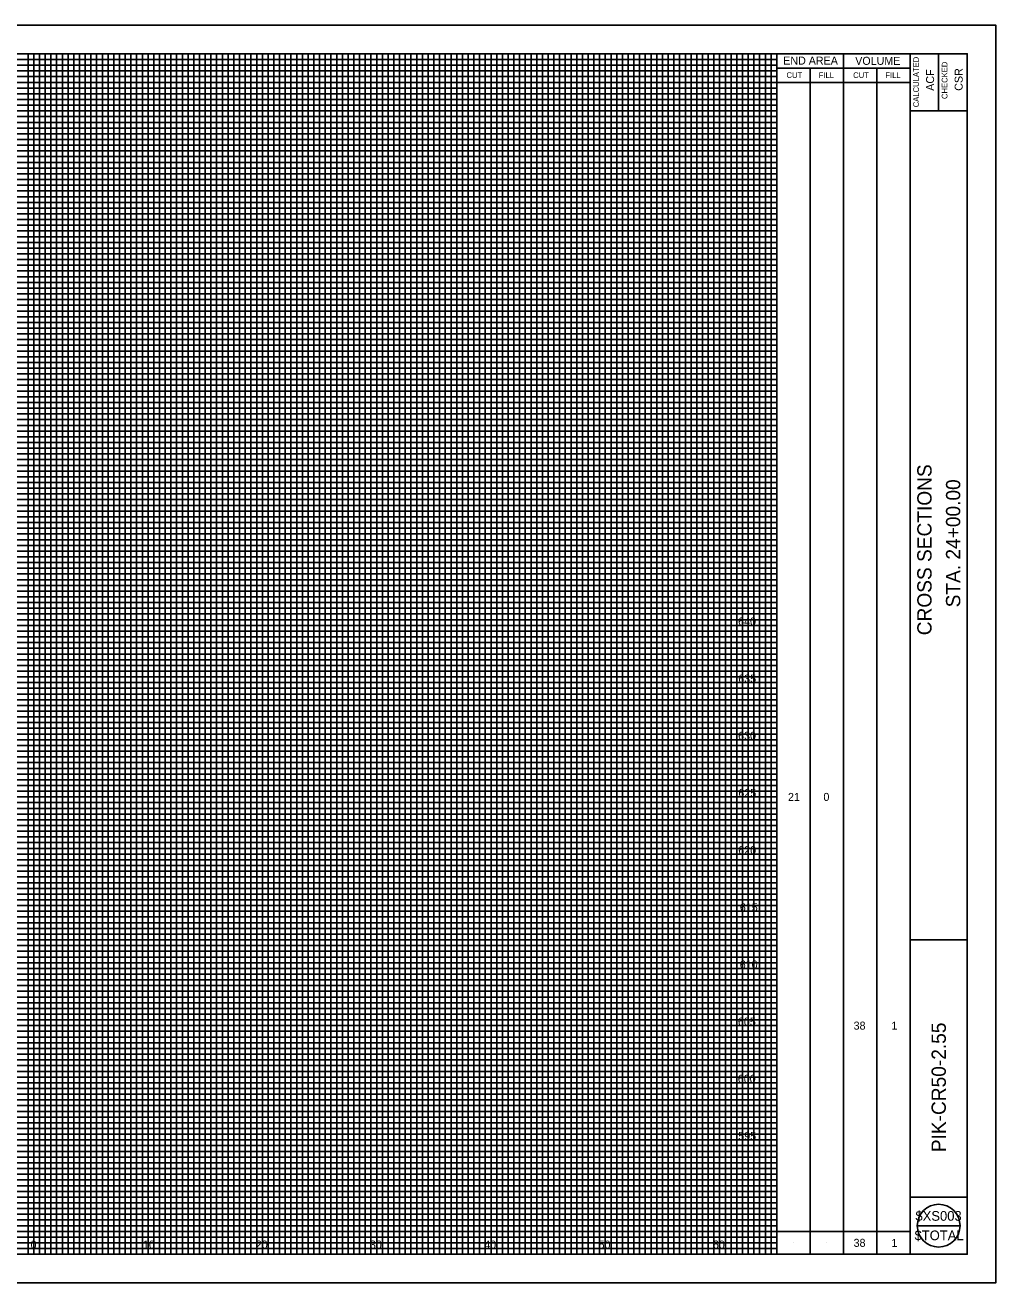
# Model space of a CAD drawing. Extents: x 1858928 to 1859278, y 421672 to 422012.
# Drawn here: x 1859012.6 to 1859097.5, y 421901.6 to 422011.6 of the extents above; entities that cross this region are included whole.
import ezdxf

# ---------------------------------------------------------------- set-up
doc = ezdxf.new("R2010")
doc.units = 0
for name, color, linetype in [('SH_Border', 7, 'Continuous'), ('SH_Cut_Line', 7, 'Continuous'), ('SH_Data', 7, 'Continuous'), ('SH_Major_Grid_Line', 7, 'Continuous'), ('SH_Minor_Grid_Line', 7, 'Continuous'), ('SH_Text', 7, 'Continuous')]:
    doc.layers.add(name, color=color, linetype=linetype)

msp = doc.modelspace()

# ---------------------------------------------------------------- linework, layer by layer
at = {"layer": 'SH_Border'}
for p, q in [((1859090.03, 421904.11), (1859090.03, 422009.11)), ((1859092.53, 422009.11), (1859092.53, 422004.11)), ((1859090.03, 422004.11), (1859095.03, 422004.11)), ((1859090.03, 421931.61), (1859095.03, 421931.61)), ((1859090.03, 421909.11), (1859095.03, 421909.11))]:
    msp.add_line(p, q, dxfattribs=at)
msp.add_lwpolyline([(1858937.53, 422009.11), (1859095.03, 422009.11), (1859095.03, 421904.11), (1858937.53, 421904.11)], close=True, dxfattribs=at)
at = {"layer": 'SH_Cut_Line'}
msp.add_lwpolyline([(1858927.53, 421901.61), (1859097.53, 421901.61), (1859097.53, 422011.61), (1858927.53, 422011.61)], close=True, dxfattribs=at)
at = {"layer": 'SH_Data'}
for p, q in [((1859078.37, 421904.11), (1859078.37, 422009.11)), ((1859084.2, 421904.11), (1859084.2, 422009.11)), ((1859078.37, 422007.86), (1859090.03, 422007.86)), ((1859081.28, 421904.11), (1859081.28, 422007.86)), ((1859087.12, 421904.11), (1859087.12, 422007.86)), ((1859078.37, 422006.61), (1859090.03, 422006.61)), ((1859078.37, 421906.11), (1859090.03, 421906.11)), ((1859090.66, 421906.61), (1859094.41, 421906.61)), ((1859079.83, 421905.11), (1859079.83, 421905.11)), ((1859082.74, 421905.11), (1859082.74, 421905.11)), ((1859085.66, 421905.11), (1859085.66, 421905.11)), ((1859088.58, 421905.11), (1859088.58, 421905.11))]:
    msp.add_line(p, q, dxfattribs=at)
msp.add_circle((1859092.53, 421906.61), 1.87, dxfattribs=at)
at = {"layer": 'SH_Major_Grid_Line'}
for p, q in [((1859013.37, 421904.11), (1859013.37, 422009.11)), ((1859018.37, 421904.11), (1859018.37, 422009.11)), ((1859023.37, 421904.11), (1859023.37, 422009.11)), ((1859028.37, 421904.11), (1859028.37, 422009.11)), ((1859033.37, 421904.11), (1859033.37, 422009.11)), ((1859038.37, 421904.11), (1859038.37, 422009.11)), ((1859043.37, 421904.11), (1859043.37, 422009.11)), ((1859048.37, 421904.11), (1859048.37, 422009.11)), ((1859053.37, 421904.11), (1859053.37, 422009.11)), ((1859058.37, 421904.11), (1859058.37, 422009.11)), ((1859063.37, 421904.11), (1859063.37, 422009.11)), ((1859068.37, 421904.11), (1859068.37, 422009.11)), ((1859073.37, 421904.11), (1859073.37, 422009.11)), ((1858943.37, 422004.11), (1859078.37, 422004.11)), ((1858943.37, 421999.11), (1859078.37, 421999.11)), ((1858943.37, 421994.11), (1859078.37, 421994.11)), ((1858943.37, 421989.11), (1859078.37, 421989.11)), ((1858943.37, 421984.11), (1859078.37, 421984.11)), ((1858943.37, 421979.11), (1859078.37, 421979.11)), ((1858943.37, 421974.11), (1859078.37, 421974.11)), ((1858943.37, 421969.11), (1859078.37, 421969.11)), ((1858943.37, 421964.11), (1859078.37, 421964.11)), ((1858943.37, 421959.11), (1859078.37, 421959.11)), ((1858943.37, 421954.11), (1859078.37, 421954.11)), ((1858943.37, 421949.11), (1859078.37, 421949.11)), ((1858943.37, 421944.11), (1859078.37, 421944.11)), ((1858943.37, 421939.11), (1859078.37, 421939.11)), ((1858943.37, 421934.11), (1859078.37, 421934.11)), ((1858943.37, 421929.11), (1859078.37, 421929.11)), ((1858943.37, 421924.11), (1859078.37, 421924.11)), ((1858943.37, 421919.11), (1859078.37, 421919.11)), ((1858943.37, 421914.11), (1859078.37, 421914.11)), ((1858943.37, 421909.11), (1859078.37, 421909.11))]:
    msp.add_line(p, q, dxfattribs=at)
at = {"layer": 'SH_Minor_Grid_Line'}
for p, q in [((1858943.37, 422008.61), (1859078.37, 422008.61)), ((1859012.87, 421904.11), (1859012.87, 422009.11)), ((1859013.87, 421904.11), (1859013.87, 422009.11)), ((1859014.37, 421904.11), (1859014.37, 422009.11)), ((1859014.87, 421904.11), (1859014.87, 422009.11)), ((1859015.37, 421904.11), (1859015.37, 422009.11)), ((1859015.87, 421904.11), (1859015.87, 422009.11)), ((1859016.37, 421904.11), (1859016.37, 422009.11)), ((1859016.87, 421904.11), (1859016.87, 422009.11)), ((1859017.37, 421904.11), (1859017.37, 422009.11)), ((1859017.87, 421904.11), (1859017.87, 422009.11)), ((1859018.87, 421904.11), (1859018.87, 422009.11)), ((1859019.37, 421904.11), (1859019.37, 422009.11)), ((1859019.87, 421904.11), (1859019.87, 422009.11)), ((1859020.37, 421904.11), (1859020.37, 422009.11)), ((1859020.87, 421904.11), (1859020.87, 422009.11)), ((1859021.37, 421904.11), (1859021.37, 422009.11)), ((1859021.87, 421904.11), (1859021.87, 422009.11)), ((1859022.37, 421904.11), (1859022.37, 422009.11)), ((1859022.87, 421904.11), (1859022.87, 422009.11)), ((1859023.87, 421904.11), (1859023.87, 422009.11)), ((1859024.37, 421904.11), (1859024.37, 422009.11)), ((1859024.87, 421904.11), (1859024.87, 422009.11)), ((1859025.37, 421904.11), (1859025.37, 422009.11)), ((1859025.87, 421904.11), (1859025.87, 422009.11)), ((1859026.37, 421904.11), (1859026.37, 422009.11)), ((1859026.87, 421904.11), (1859026.87, 422009.11)), ((1859027.37, 421904.11), (1859027.37, 422009.11)), ((1859027.87, 421904.11), (1859027.87, 422009.11)), ((1859028.87, 421904.11), (1859028.87, 422009.11)), ((1859029.37, 421904.11), (1859029.37, 422009.11)), ((1859029.87, 421904.11), (1859029.87, 422009.11)), ((1859030.37, 421904.11), (1859030.37, 422009.11)), ((1859030.87, 421904.11), (1859030.87, 422009.11)), ((1859031.37, 421904.11), (1859031.37, 422009.11)), ((1859031.87, 421904.11), (1859031.87, 422009.11)), ((1859032.37, 421904.11), (1859032.37, 422009.11)), ((1859032.87, 421904.11), (1859032.87, 422009.11)), ((1859033.87, 421904.11), (1859033.87, 422009.11)), ((1859034.37, 421904.11), (1859034.37, 422009.11)), ((1859034.87, 421904.11), (1859034.87, 422009.11)), ((1859035.37, 421904.11), (1859035.37, 422009.11)), ((1859035.87, 421904.11), (1859035.87, 422009.11)), ((1859036.37, 421904.11), (1859036.37, 422009.11)), ((1859036.87, 421904.11), (1859036.87, 422009.11)), ((1859037.37, 421904.11), (1859037.37, 422009.11)), ((1859037.87, 421904.11), (1859037.87, 422009.11)), ((1859038.87, 421904.11), (1859038.87, 422009.11)), ((1859039.37, 421904.11), (1859039.37, 422009.11)), ((1859039.87, 421904.11), (1859039.87, 422009.11)), ((1859040.37, 421904.11), (1859040.37, 422009.11)), ((1859040.87, 421904.11), (1859040.87, 422009.11)), ((1859041.37, 421904.11), (1859041.37, 422009.11)), ((1859041.87, 421904.11), (1859041.87, 422009.11)), ((1859042.37, 421904.11), (1859042.37, 422009.11)), ((1859042.87, 421904.11), (1859042.87, 422009.11)), ((1859043.87, 421904.11), (1859043.87, 422009.11)), ((1859044.37, 421904.11), (1859044.37, 422009.11)), ((1859044.87, 421904.11), (1859044.87, 422009.11)), ((1859045.37, 421904.11), (1859045.37, 422009.11)), ((1859045.87, 421904.11), (1859045.87, 422009.11)), ((1859046.37, 421904.11), (1859046.37, 422009.11)), ((1859046.87, 421904.11), (1859046.87, 422009.11)), ((1859047.37, 421904.11), (1859047.37, 422009.11)), ((1859047.87, 421904.11), (1859047.87, 422009.11)), ((1859048.87, 421904.11), (1859048.87, 422009.11)), ((1859049.37, 421904.11), (1859049.37, 422009.11)), ((1859049.87, 421904.11), (1859049.87, 422009.11)), ((1859050.37, 421904.11), (1859050.37, 422009.11)), ((1859050.87, 421904.11), (1859050.87, 422009.11)), ((1859051.37, 421904.11), (1859051.37, 422009.11)), ((1859051.87, 421904.11), (1859051.87, 422009.11)), ((1859052.37, 421904.11), (1859052.37, 422009.11)), ((1859052.87, 421904.11), (1859052.87, 422009.11)), ((1859053.87, 421904.11), (1859053.87, 422009.11)), ((1859054.37, 421904.11), (1859054.37, 422009.11)), ((1859054.87, 421904.11), (1859054.87, 422009.11)), ((1859055.37, 421904.11), (1859055.37, 422009.11)), ((1859055.87, 421904.11), (1859055.87, 422009.11)), ((1859056.37, 421904.11), (1859056.37, 422009.11)), ((1859056.87, 421904.11), (1859056.87, 422009.11)), ((1859057.37, 421904.11), (1859057.37, 422009.11)), ((1859057.87, 421904.11), (1859057.87, 422009.11)), ((1859058.87, 421904.11), (1859058.87, 422009.11)), ((1859059.37, 421904.11), (1859059.37, 422009.11)), ((1859059.87, 421904.11), (1859059.87, 422009.11)), ((1859060.37, 421904.11), (1859060.37, 422009.11)), ((1859060.87, 421904.11), (1859060.87, 422009.11)), ((1859061.37, 421904.11), (1859061.37, 422009.11)), ((1859061.87, 421904.11), (1859061.87, 422009.11)), ((1859062.37, 421904.11), (1859062.37, 422009.11)), ((1859062.87, 421904.11), (1859062.87, 422009.11)), ((1859063.87, 421904.11), (1859063.87, 422009.11)), ((1859064.37, 421904.11), (1859064.37, 422009.11)), ((1859064.87, 421904.11), (1859064.87, 422009.11)), ((1859065.37, 421904.11), (1859065.37, 422009.11)), ((1859065.87, 421904.11), (1859065.87, 422009.11)), ((1859066.37, 421904.11), (1859066.37, 422009.11)), ((1859066.87, 421904.11), (1859066.87, 422009.11)), ((1859067.37, 421904.11), (1859067.37, 422009.11)), ((1859067.87, 421904.11), (1859067.87, 422009.11)), ((1859068.87, 421904.11), (1859068.87, 422009.11)), ((1859069.37, 421904.11), (1859069.37, 422009.11)), ((1859069.87, 421904.11), (1859069.87, 422009.11)), ((1859070.37, 421904.11), (1859070.37, 422009.11)), ((1859070.87, 421904.11), (1859070.87, 422009.11)), ((1859071.37, 421904.11), (1859071.37, 422009.11)), ((1859071.87, 421904.11), (1859071.87, 422009.11)), ((1859072.37, 421904.11), (1859072.37, 422009.11)), ((1859072.87, 421904.11), (1859072.87, 422009.11)), ((1859073.87, 421904.11), (1859073.87, 422009.11)), ((1859074.37, 421904.11), (1859074.37, 422009.11)), ((1859074.87, 421904.11), (1859074.87, 422009.11)), ((1859075.37, 421904.11), (1859075.37, 422009.11)), ((1859075.87, 421904.11), (1859075.87, 422009.11)), ((1859076.37, 421904.11), (1859076.37, 422009.11)), ((1859076.87, 421904.11), (1859076.87, 422009.11)), ((1859077.37, 421904.11), (1859077.37, 422009.11)), ((1859077.87, 421904.11), (1859077.87, 422009.11)), ((1858943.37, 422008.11), (1859078.37, 422008.11)), ((1858943.37, 422007.61), (1859078.37, 422007.61)), ((1858943.37, 422007.11), (1859078.37, 422007.11)), ((1858943.37, 422006.61), (1859078.37, 422006.61)), ((1858943.37, 422006.11), (1859078.37, 422006.11)), ((1858943.37, 422005.61), (1859078.37, 422005.61)), ((1858943.37, 422005.11), (1859078.37, 422005.11)), ((1858943.37, 422004.61), (1859078.37, 422004.61)), ((1858943.37, 422003.61), (1859078.37, 422003.61)), ((1858943.37, 422003.11), (1859078.37, 422003.11)), ((1858943.37, 422002.61), (1859078.37, 422002.61)), ((1858943.37, 422002.11), (1859078.37, 422002.11)), ((1858943.37, 422001.61), (1859078.37, 422001.61)), ((1858943.37, 422001.11), (1859078.37, 422001.11)), ((1858943.37, 422000.61), (1859078.37, 422000.61)), ((1858943.37, 422000.11), (1859078.37, 422000.11)), ((1858943.37, 421999.61), (1859078.37, 421999.61)), ((1858943.37, 421998.61), (1859078.37, 421998.61)), ((1858943.37, 421998.11), (1859078.37, 421998.11)), ((1858943.37, 421997.61), (1859078.37, 421997.61)), ((1858943.37, 421997.11), (1859078.37, 421997.11)), ((1858943.37, 421996.61), (1859078.37, 421996.61)), ((1858943.37, 421996.11), (1859078.37, 421996.11)), ((1858943.37, 421995.61), (1859078.37, 421995.61)), ((1858943.37, 421995.11), (1859078.37, 421995.11)), ((1858943.37, 421994.61), (1859078.37, 421994.61)), ((1858943.37, 421993.61), (1859078.37, 421993.61)), ((1858943.37, 421993.11), (1859078.37, 421993.11)), ((1858943.37, 421992.61), (1859078.37, 421992.61)), ((1858943.37, 421992.11), (1859078.37, 421992.11)), ((1858943.37, 421991.61), (1859078.37, 421991.61)), ((1858943.37, 421991.11), (1859078.37, 421991.11)), ((1858943.37, 421990.61), (1859078.37, 421990.61)), ((1858943.37, 421990.11), (1859078.37, 421990.11)), ((1858943.37, 421989.61), (1859078.37, 421989.61)), ((1858943.37, 421988.61), (1859078.37, 421988.61)), ((1858943.37, 421988.11), (1859078.37, 421988.11)), ((1858943.37, 421987.61), (1859078.37, 421987.61)), ((1858943.37, 421987.11), (1859078.37, 421987.11)), ((1858943.37, 421986.61), (1859078.37, 421986.61)), ((1858943.37, 421986.11), (1859078.37, 421986.11)), ((1858943.37, 421985.61), (1859078.37, 421985.61)), ((1858943.37, 421985.11), (1859078.37, 421985.11)), ((1858943.37, 421984.61), (1859078.37, 421984.61)), ((1858943.37, 421983.61), (1859078.37, 421983.61)), ((1858943.37, 421983.11), (1859078.37, 421983.11)), ((1858943.37, 421982.61), (1859078.37, 421982.61)), ((1858943.37, 421982.11), (1859078.37, 421982.11)), ((1858943.37, 421981.61), (1859078.37, 421981.61)), ((1858943.37, 421981.11), (1859078.37, 421981.11)), ((1858943.37, 421980.61), (1859078.37, 421980.61)), ((1858943.37, 421980.11), (1859078.37, 421980.11)), ((1858943.37, 421979.61), (1859078.37, 421979.61)), ((1858943.37, 421978.61), (1859078.37, 421978.61)), ((1858943.37, 421978.11), (1859078.37, 421978.11)), ((1858943.37, 421977.61), (1859078.37, 421977.61)), ((1858943.37, 421977.11), (1859078.37, 421977.11)), ((1858943.37, 421976.61), (1859078.37, 421976.61)), ((1858943.37, 421976.11), (1859078.37, 421976.11)), ((1858943.37, 421975.61), (1859078.37, 421975.61)), ((1858943.37, 421975.11), (1859078.37, 421975.11)), ((1858943.37, 421974.61), (1859078.37, 421974.61)), ((1858943.37, 421973.61), (1859078.37, 421973.61)), ((1858943.37, 421973.11), (1859078.37, 421973.11)), ((1858943.37, 421972.61), (1859078.37, 421972.61)), ((1858943.37, 421972.11), (1859078.37, 421972.11)), ((1858943.37, 421971.61), (1859078.37, 421971.61)), ((1858943.37, 421971.11), (1859078.37, 421971.11)), ((1858943.37, 421970.61), (1859078.37, 421970.61)), ((1858943.37, 421970.11), (1859078.37, 421970.11)), ((1858943.37, 421969.61), (1859078.37, 421969.61)), ((1858943.37, 421968.61), (1859078.37, 421968.61)), ((1858943.37, 421968.11), (1859078.37, 421968.11)), ((1858943.37, 421967.61), (1859078.37, 421967.61)), ((1858943.37, 421967.11), (1859078.37, 421967.11)), ((1858943.37, 421966.61), (1859078.37, 421966.61)), ((1858943.37, 421966.11), (1859078.37, 421966.11)), ((1858943.37, 421965.61), (1859078.37, 421965.61)), ((1858943.37, 421965.11), (1859078.37, 421965.11)), ((1858943.37, 421964.61), (1859078.37, 421964.61)), ((1858943.37, 421963.61), (1859078.37, 421963.61)), ((1858943.37, 421963.11), (1859078.37, 421963.11)), ((1858943.37, 421962.61), (1859078.37, 421962.61)), ((1858943.37, 421962.11), (1859078.37, 421962.11)), ((1858943.37, 421961.61), (1859078.37, 421961.61)), ((1858943.37, 421961.11), (1859078.37, 421961.11)), ((1858943.37, 421960.61), (1859078.37, 421960.61)), ((1858943.37, 421960.11), (1859078.37, 421960.11)), ((1858943.37, 421959.61), (1859078.37, 421959.61)), ((1858943.37, 421958.61), (1859078.37, 421958.61)), ((1858943.37, 421958.11), (1859078.37, 421958.11)), ((1858943.37, 421957.61), (1859078.37, 421957.61)), ((1858943.37, 421957.11), (1859078.37, 421957.11)), ((1858943.37, 421956.61), (1859078.37, 421956.61)), ((1858943.37, 421956.11), (1859078.37, 421956.11)), ((1858943.37, 421955.61), (1859078.37, 421955.61)), ((1858943.37, 421955.11), (1859078.37, 421955.11)), ((1858943.37, 421954.61), (1859078.37, 421954.61)), ((1858943.37, 421953.61), (1859078.37, 421953.61)), ((1858943.37, 421953.11), (1859078.37, 421953.11)), ((1858943.37, 421952.61), (1859078.37, 421952.61)), ((1858943.37, 421952.11), (1859078.37, 421952.11)), ((1858943.37, 421951.61), (1859078.37, 421951.61)), ((1858943.37, 421951.11), (1859078.37, 421951.11)), ((1858943.37, 421950.61), (1859078.37, 421950.61)), ((1858943.37, 421950.11), (1859078.37, 421950.11)), ((1858943.37, 421949.61), (1859078.37, 421949.61)), ((1858943.37, 421948.61), (1859078.37, 421948.61)), ((1858943.37, 421948.11), (1859078.37, 421948.11)), ((1858943.37, 421947.61), (1859078.37, 421947.61)), ((1858943.37, 421947.11), (1859078.37, 421947.11)), ((1858943.37, 421946.61), (1859078.37, 421946.61)), ((1858943.37, 421946.11), (1859078.37, 421946.11)), ((1858943.37, 421945.61), (1859078.37, 421945.61)), ((1858943.37, 421945.11), (1859078.37, 421945.11)), ((1858943.37, 421944.61), (1859078.37, 421944.61)), ((1858943.37, 421943.61), (1859078.37, 421943.61)), ((1858943.37, 421943.11), (1859078.37, 421943.11)), ((1858943.37, 421942.61), (1859078.37, 421942.61)), ((1858943.37, 421942.11), (1859078.37, 421942.11)), ((1858943.37, 421941.61), (1859078.37, 421941.61)), ((1858943.37, 421941.11), (1859078.37, 421941.11)), ((1858943.37, 421940.61), (1859078.37, 421940.61)), ((1858943.37, 421940.11), (1859078.37, 421940.11)), ((1858943.37, 421939.61), (1859078.37, 421939.61)), ((1858943.37, 421938.61), (1859078.37, 421938.61)), ((1858943.37, 421938.11), (1859078.37, 421938.11)), ((1858943.37, 421937.61), (1859078.37, 421937.61)), ((1858943.37, 421937.11), (1859078.37, 421937.11)), ((1858943.37, 421936.61), (1859078.37, 421936.61)), ((1858943.37, 421936.11), (1859078.37, 421936.11)), ((1858943.37, 421935.61), (1859078.37, 421935.61)), ((1858943.37, 421935.11), (1859078.37, 421935.11)), ((1858943.37, 421934.61), (1859078.37, 421934.61)), ((1858943.37, 421933.61), (1859078.37, 421933.61)), ((1858943.37, 421933.11), (1859078.37, 421933.11)), ((1858943.37, 421932.61), (1859078.37, 421932.61)), ((1858943.37, 421932.11), (1859078.37, 421932.11)), ((1858943.37, 421931.61), (1859078.37, 421931.61)), ((1858943.37, 421931.11), (1859078.37, 421931.11)), ((1858943.37, 421930.61), (1859078.37, 421930.61)), ((1858943.37, 421930.11), (1859078.37, 421930.11)), ((1858943.37, 421929.61), (1859078.37, 421929.61)), ((1858943.37, 421928.61), (1859078.37, 421928.61)), ((1858943.37, 421928.11), (1859078.37, 421928.11)), ((1858943.37, 421927.61), (1859078.37, 421927.61)), ((1858943.37, 421927.11), (1859078.37, 421927.11)), ((1858943.37, 421926.61), (1859078.37, 421926.61)), ((1858943.37, 421926.11), (1859078.37, 421926.11)), ((1858943.37, 421925.61), (1859078.37, 421925.61)), ((1858943.37, 421925.11), (1859078.37, 421925.11)), ((1858943.37, 421924.61), (1859078.37, 421924.61)), ((1858943.37, 421923.61), (1859078.37, 421923.61)), ((1858943.37, 421923.11), (1859078.37, 421923.11)), ((1858943.37, 421922.61), (1859078.37, 421922.61)), ((1858943.37, 421922.11), (1859078.37, 421922.11)), ((1858943.37, 421921.61), (1859078.37, 421921.61)), ((1858943.37, 421921.11), (1859078.37, 421921.11)), ((1858943.37, 421920.61), (1859078.37, 421920.61)), ((1858943.37, 421920.11), (1859078.37, 421920.11)), ((1858943.37, 421919.61), (1859078.37, 421919.61)), ((1858943.37, 421918.61), (1859078.37, 421918.61)), ((1858943.37, 421918.11), (1859078.37, 421918.11)), ((1858943.37, 421917.61), (1859078.37, 421917.61)), ((1858943.37, 421917.11), (1859078.37, 421917.11)), ((1858943.37, 421916.61), (1859078.37, 421916.61)), ((1858943.37, 421916.11), (1859078.37, 421916.11)), ((1858943.37, 421915.61), (1859078.37, 421915.61)), ((1858943.37, 421915.11), (1859078.37, 421915.11)), ((1858943.37, 421914.61), (1859078.37, 421914.61)), ((1858943.37, 421913.61), (1859078.37, 421913.61)), ((1858943.37, 421913.11), (1859078.37, 421913.11)), ((1858943.37, 421912.61), (1859078.37, 421912.61)), ((1858943.37, 421912.11), (1859078.37, 421912.11)), ((1858943.37, 421911.61), (1859078.37, 421911.61)), ((1858943.37, 421911.11), (1859078.37, 421911.11)), ((1858943.37, 421910.61), (1859078.37, 421910.61)), ((1858943.37, 421910.11), (1859078.37, 421910.11)), ((1858943.37, 421909.61), (1859078.37, 421909.61)), ((1858943.37, 421908.61), (1859078.37, 421908.61)), ((1858943.37, 421908.11), (1859078.37, 421908.11)), ((1858943.37, 421907.61), (1859078.37, 421907.61)), ((1858943.37, 421907.11), (1859078.37, 421907.11)), ((1858943.37, 421906.61), (1859078.37, 421906.61)), ((1858943.37, 421906.11), (1859078.37, 421906.11)), ((1858943.37, 421905.61), (1859078.37, 421905.61)), ((1858943.37, 421905.11), (1859078.37, 421905.11)), ((1858943.37, 421904.61), (1859078.37, 421904.61))]:
    msp.add_line(p, q, dxfattribs=at)

# ---------------------------------------------------------------- texts
at = {"layer": 'SH_Data'}
for s, height, p in [('END AREA', 0.7, (1859078.93, 422008.16)), ('VOLUME', 0.7, (1859085.23, 422008.14)), ('CUT', 0.5, (1859079.22, 422006.99)), ('FILL', 0.5, (1859082.04, 422006.99)), ('CUT', 0.5, (1859085.05, 422006.99)), ('FILL', 0.5, (1859087.87, 422006.99)), ('$XS003', 0.85, (1859090.5, 421907.04)), ('$TOTAL', 0.85, (1859090.42, 421905.34))]:
    msp.add_text(s, height=height, dxfattribs=at).set_placement(p)
for s, height, p in [('CALCULATED', 0.5, (1859090.8, 422004.43)), ('ACF', 0.7, (1859092.13, 422005.87)), ('CHECKED', 0.5, (1859093.3, 422005.15)), ('CSR', 0.7, (1859094.63, 422005.87)), ('CROSS SECTIONS', 1.25, (1859091.91, 421958.25)), ('STA. 24+00.00', 1.25, (1859094.42, 421960.69)), ('PIK-CR50-2.55', 1.25, (1859093.16, 421913.04))]:
    msp.add_text(s, height=height, rotation=90, dxfattribs=at).set_placement(p)
at = {"layer": 'SH_Text'}
for s, p in [('640', (1859074.99, 421959.11)), ('635', (1859075, 421954.11)), ('630', (1859074.99, 421949.11)), ('625', (1859075.01, 421944.11)), ('21', (1859079.35, 421943.76)), ('0', (1859082.45, 421943.76)), ('620', (1859075, 421939.11)), ('615', (1859075.14, 421934.11)), ('610', (1859075.13, 421929.11)), ('605', (1859074.97, 421924.11)), ('38', (1859085.09, 421923.76)), ('1', (1859088.4, 421923.76)), ('600', (1859074.96, 421919.11)), ('595', (1859075, 421914.11)), ('0', (1859013.09, 421904.61)), ('0', (1859013.09, 421904.61)), ('10', (1859022.92, 421904.61)), ('20', (1859032.79, 421904.61)), ('30', (1859042.78, 421904.61)), ('40', (1859052.78, 421904.61)), ('50', (1859062.78, 421904.61)), ('60', (1859072.78, 421904.61)), ('38', (1859085.09, 421904.76)), ('1', (1859088.4, 421904.76))]:
    msp.add_text(s, height=0.7, dxfattribs=at).set_placement(p)

doc.saveas('drawing.dxf')
